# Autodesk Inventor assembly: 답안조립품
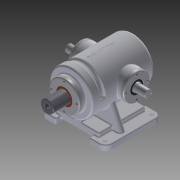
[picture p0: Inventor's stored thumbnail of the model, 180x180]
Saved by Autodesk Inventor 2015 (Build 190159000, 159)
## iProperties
Created: 2015-10
Part Number: 답안조립품
Document SubType Name: Assembly
Designer: youjin08
Mass: 9437.36 g
Surface Area: 4327.34 cm^2
Volume: 2315.26 cm^3
Density: 4.07615 g/cm^3
Author: youjin08
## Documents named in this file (13)
- C:\Users\youjin08\Desktop\351019V1013\답안조립품.iam
- C:\Users\youjin08\Desktop\351019V1013\본체.ipt
- C:\Users\youjin08\Desktop\351019V1013\슬라이드 커버.ipt
- C:\Users\youjin08\Desktop\351019V1013\M4x0.7.ipt
- C:\Users\youjin08\Desktop\351019V1013\축 커버.ipt
- C:\Users\youjin08\Desktop\351019V1013\오일실.ipt
- 오일실.ipt
- C:\Users\youjin08\Desktop\351019V1013\베어링 6205.ipt
- 베어링 6205.ipt
- C:\Users\youjin08\Desktop\351019V1013\편심축.ipt
- C:\Users\youjin08\Desktop\351019V1013\부시.ipt
- C:\Users\youjin08\Desktop\351019V1013\가변스프링.ipt
- C:\Users\youjin08\Desktop\351019V1013\슬라이드.ipt
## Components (13 placed, 2 different names)
1. 가변스프링:1 — Mate:20, Mate:21, Mate:22, Mate:23
2. M4x0.7:1 — Insert:1
3. M4x0.7:4
4. M4x0.7:5
5. M4x0.7:6
6. M4x0.7:3 — Insert:3
7. M4x0.7:2 — Insert:2
8. M4x0.7:7
9. M4x0.7:8
10. M4x0.7:9
11. M4x0.7:10
12. M4x0.7:11
13. M4x0.7:12
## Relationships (7: Mate 4, Insert 3)
- Insert:1: M4x0.7:1
- Insert:2: M4x0.7:2
- Insert:3: M4x0.7:3
- Mate:20: 가변스프링:1
- Mate:21: 가변스프링:1
- Mate:22: 가변스프링:1
- Mate:23: 가변스프링:1
